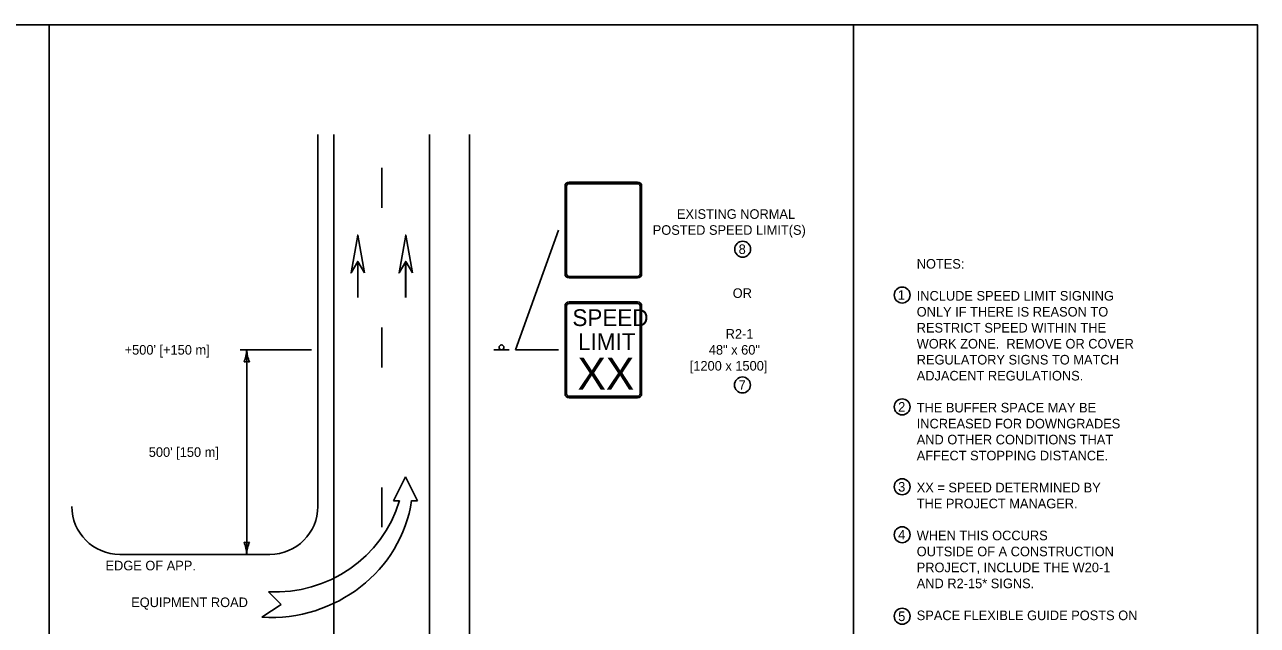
# Model space of a CAD drawing. Extents: x 49991.4 to 50021, y 49987.6 to 50011.4.
# Drawn here: x 50009.03 to 50016.75, y 49995.24 to 49999 of the extents above; entities that cross this region are included whole.
import ezdxf

# ---------------------------------------------------------------- set-up
doc = ezdxf.new("R2010")
doc.units = 0
for name, color, linetype in [('Level 1', 7, 'Continuous'), ('Level 2', 7, 'Continuous'), ('Level 3', 7, 'Continuous')]:
    doc.layers.add(name, color=color, linetype=linetype)

msp = doc.modelspace()

# ---------------------------------------------------------------- linework, layer by layer
at = {"layer": 'Level 1'}
for p, q in [((50010.8663, 49995.9842), (50010.8663, 49998.3116)), ((50010.9663, 49989.324), (50010.9663, 49998.3116)), ((50011.5663, 49989.324), (50011.5663, 49998.3116)), ((50011.8163, 49989.324), (50011.8163, 49998.3116)), ((50011.2663, 49997.8534), (50011.2663, 49998.1034)), ((50012.4143, 49997.439), (50012.4143, 49997.989)), ((50012.4243, 49997.439), (50012.4243, 49997.989)), ((50012.4393, 49998.014), (50012.8693, 49998.014)), ((50012.4393, 49998.004), (50012.8693, 49998.004)), ((50012.8843, 49997.989), (50012.8843, 49997.439)), ((50012.8943, 49997.989), (50012.8943, 49997.439)), ((50011.1163, 49997.292), (50011.1163, 49997.518)), ((50011.1166, 49997.292), (50011.1166, 49997.518)), ((50011.4163, 49997.292), (50011.4163, 49997.518)), ((50011.4166, 49997.292), (50011.4166, 49997.518)), ((50012.8693, 49997.424), (50012.4393, 49997.424)), ((50012.8693, 49997.414), (50012.4393, 49997.414)), ((50012.4393, 49997.2642), (50012.8693, 49997.2642)), ((50012.4393, 49997.2542), (50012.8693, 49997.2542)), ((50012.4143, 49996.6892), (50012.4143, 49997.2392)), ((50012.4243, 49996.6892), (50012.4243, 49997.2392)), ((50012.8843, 49997.2392), (50012.8843, 49996.6892)), ((50012.8943, 49997.2392), (50012.8943, 49996.6892)), ((50011.2663, 49996.8534), (50011.2663, 49997.1034)), ((50012.0643, 49996.9642), (50011.9683, 49996.9642)), ((50012.8693, 49996.6742), (50012.4393, 49996.6742)), ((50012.8693, 49996.6642), (50012.4393, 49996.6642)), ((50011.2663, 49995.8534), (50011.2663, 49996.1034)), ((50011.3412, 49996.0202), (50011.4162, 49996.1702)), ((50011.4162, 49996.1702), (50011.3412, 49996.0202)), ((50011.4162, 49996.1702), (50011.4912, 49996.0202)), ((50011.4912, 49996.0202), (50011.4162, 49996.1702)), ((50011.3412, 49996.0202), (50011.3787, 49996.0202)), ((50011.3412, 49996.0202), (50011.3787, 49996.0202)), ((50011.4537, 49996.0202), (50011.4912, 49996.0202)), ((50011.4537, 49996.0202), (50011.4912, 49996.0202)), ((50009.6257, 49995.6842), (50010.5663, 49995.6842)), ((50010.5565, 49995.4502), (50010.6365, 49995.3702)), ((50010.5565, 49995.4502), (50010.6365, 49995.3702)), ((50010.6365, 49995.3702), (50010.5165, 49995.2902)), ((50010.6365, 49995.3702), (50010.5165, 49995.2902))]:
    msp.add_line(p, q, dxfattribs=at)
for points in [[(49999.3835, 49998.9992), (50016.7501, 49998.9992), (50016.7501, 49987.7988), (49999.3835, 49987.7988)], [(50011.1583, 49997.4456), (50011.1166, 49997.6822), (50011.0747, 49997.4456), (50011.1166, 49997.5178)], [(50011.4583, 49997.4456), (50011.4166, 49997.6822), (50011.3747, 49997.4456), (50011.4166, 49997.5178)]]:
    msp.add_lwpolyline(points, close=True, dxfattribs=at)
msp.add_circle((50012.0164, 49996.9793), 0.0152, dxfattribs=at)
for centre, radius, start, end in [((50012.4393, 49997.989), 0.025, 90, 180), ((50012.4393, 49997.989), 0.015, 90, 180), ((50012.8693, 49997.989), 0.025, 0, 90), ((50012.8693, 49997.989), 0.015, 0, 90), ((50012.4393, 49997.439), 0.025, 180, 270), ((50012.4393, 49997.439), 0.015, 180, 270), ((50012.8693, 49997.439), 0.025, 270, 0), ((50012.8693, 49997.439), 0.015, 270, 0), ((50012.4393, 49997.239), 0.025, 90, 180), ((50012.4393, 49997.239), 0.015, 90, 180), ((50012.8693, 49997.239), 0.025, 0, 90), ((50012.8693, 49997.239), 0.015, 0, 90), ((50012.4393, 49996.689), 0.025, 180, 270), ((50012.4393, 49996.689), 0.015, 180, 270), ((50012.8693, 49996.689), 0.025, 270, 0), ((50012.8693, 49996.689), 0.015, 270, 0), ((50010.603, 49996.2612), 0.8123, 266.71875, 342.74545), ((50010.603, 49996.2612), 0.8123, 266.71875, 342.74545), ((50009.6257, 49995.9843), 0.3, 180, 270), ((50010.5663, 49995.9843), 0.3, 270, 0)]:
    msp.add_arc(centre, radius, start, end, dxfattribs=at)
msp.add_ellipse((50010.5702, 49996.1436), major_axis=(-0.8929, 0), ratio=0.957332, start_param=1.510735, end_param=2.996867, dxfattribs=at)
msp.add_ellipse((50010.5702, 49996.1436), major_axis=(-0.8929, 0), ratio=0.957332, start_param=1.510735, end_param=2.996867, dxfattribs=at)
at = {"layer": 'Level 2'}
for centre in [(50013.5268, 49997.594), (50014.5258, 49997.3072), (50013.5255, 49996.7442), (50014.5258, 49996.6072), (50014.5258, 49996.1072), (50014.5258, 49995.8072), (50014.5258, 49995.2967)]:
    msp.add_circle(centre, 0.05, dxfattribs=at)
at = {"layer": 'Level 3'}
for p, q in [((50009.1835, 49998.9992), (50009.1835, 49987.7988)), ((50014.2203, 49998.9992), (50014.2203, 49988.2257)), ((50012.3743, 49997.714), (50012.1043, 49996.9642)), ((50010.3809, 49996.9642), (50010.8263, 49996.9642)), ((50010.4209, 49996.3242), (50010.4209, 49996.9642)), ((50012.1043, 49996.9642), (50012.3743, 49996.9642)), ((50010.4209, 49995.6842), (50010.4209, 49996.3242))]:
    msp.add_line(p, q, dxfattribs=at)
for centre, radius, start, end in [((50010.1988, 49996.9733), 0.2223, 337.45601, 357.63952), ((50010.6537, 49996.9756), 0.233, 182.82731, 202.07716), ((50010.4209, 49996.8359), 0.0548, 72.13882, 107.86118), ((50010.4209, 49995.8124), 0.0548, 252.13882, 287.86118), ((50010.1882, 49995.6727), 0.233, 2.82731, 22.07716), ((50010.6431, 49995.675), 0.2223, 157.45601, 177.63952)]:
    msp.add_arc(centre, radius, start, end, dxfattribs=at)

# ---------------------------------------------------------------- texts
at = {"layer": 'Level 1'}
for s, height, p in [('SPEED', 0.10512, (50012.4606, 49997.1129)), ('LIMIT', 0.10512, (50012.496, 49996.9627)), ('XX', 0.1989, (50012.4928, 49996.7155))]:
    msp.add_text(s, height=height, dxfattribs=at).set_placement(p)
at = {"layer": 'Level 2'}
for s, p in [('EXISTING NORMAL', (50013.1151, 49997.784)), ('POSTED SPEED LIMIT(S)', (50012.9637, 49997.684)), ('8', (50013.5018, 49997.564)), ('NOTES:', (50014.6169, 49997.4724)), ('OR', (50013.4646, 49997.2891)), ('1', (50014.4985, 49997.2772)), ('INCLUDE SPEED LIMIT SIGNING', (50014.6169, 49997.2724)), ('ONLY IF THERE IS REASON TO', (50014.6169, 49997.1724)), ('RESTRICT SPEED WITHIN THE', (50014.6169, 49997.0724)), ('R2-1', (50013.4205, 49997.0342)), ('WORK ZONE.  REMOVE OR COVER', (50014.6169, 49996.9724)), ("+500' [+150 m]", (50009.6563, 49996.9342)), ('48" x 60"', (50013.3149, 49996.9342)), ('[1200 x 1500]', (50013.1955, 49996.8342)), ('REGULATORY SIGNS TO MATCH', (50014.6169, 49996.8724)), ('ADJACENT REGULATIONS.', (50014.6169, 49996.7724)), ('7', (50013.5017, 49996.7142)), ('2', (50014.5008, 49996.5772)), ('THE BUFFER SPACE MAY BE', (50014.6169, 49996.5724)), ('INCREASED FOR DOWNGRADES', (50014.6169, 49996.4724)), ('AND OTHER CONDITIONS THAT', (50014.6169, 49996.3724)), ("500' [150 m]", (50009.8076, 49996.2942)), ('AFFECT STOPPING DISTANCE.', (50014.6169, 49996.2724)), ('3', (50014.5006, 49996.0768)), ('XX = SPEED DETERMINED BY', (50014.6169, 49996.0724)), ('THE PROJECT MANAGER.', (50014.6169, 49995.9724)), ('4', (50014.5008, 49995.7772)), ('WHEN THIS OCCURS', (50014.6169, 49995.7724)), ('OUTSIDE OF A CONSTRUCTION', (50014.6169, 49995.6724)), ('EDGE OF APP.', (50009.5365, 49995.5842)), ('PROJECT, INCLUDE THE W20-1', (50014.6169, 49995.5724)), ('AND R2-15* SIGNS.', (50014.6169, 49995.4724)), ('EQUIPMENT ROAD', (50009.6974, 49995.3542)), ('5', (50014.5008, 49995.2667)), ('SPACE FLEXIBLE GUIDE POSTS ON', (50014.6169, 49995.2724))]:
    msp.add_text(s, height=0.06, dxfattribs=at).set_placement(p)

doc.saveas('drawing.dxf')
